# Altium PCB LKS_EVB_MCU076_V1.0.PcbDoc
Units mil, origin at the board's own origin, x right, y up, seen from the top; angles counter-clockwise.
Board outline 2625 x 1560 mil, 2 copper layers (Top Layer, Bottom Layer); 44 components, 69 nets, 198 pads, 50 vias.
Unrouted connection lines stored in the file: 4.
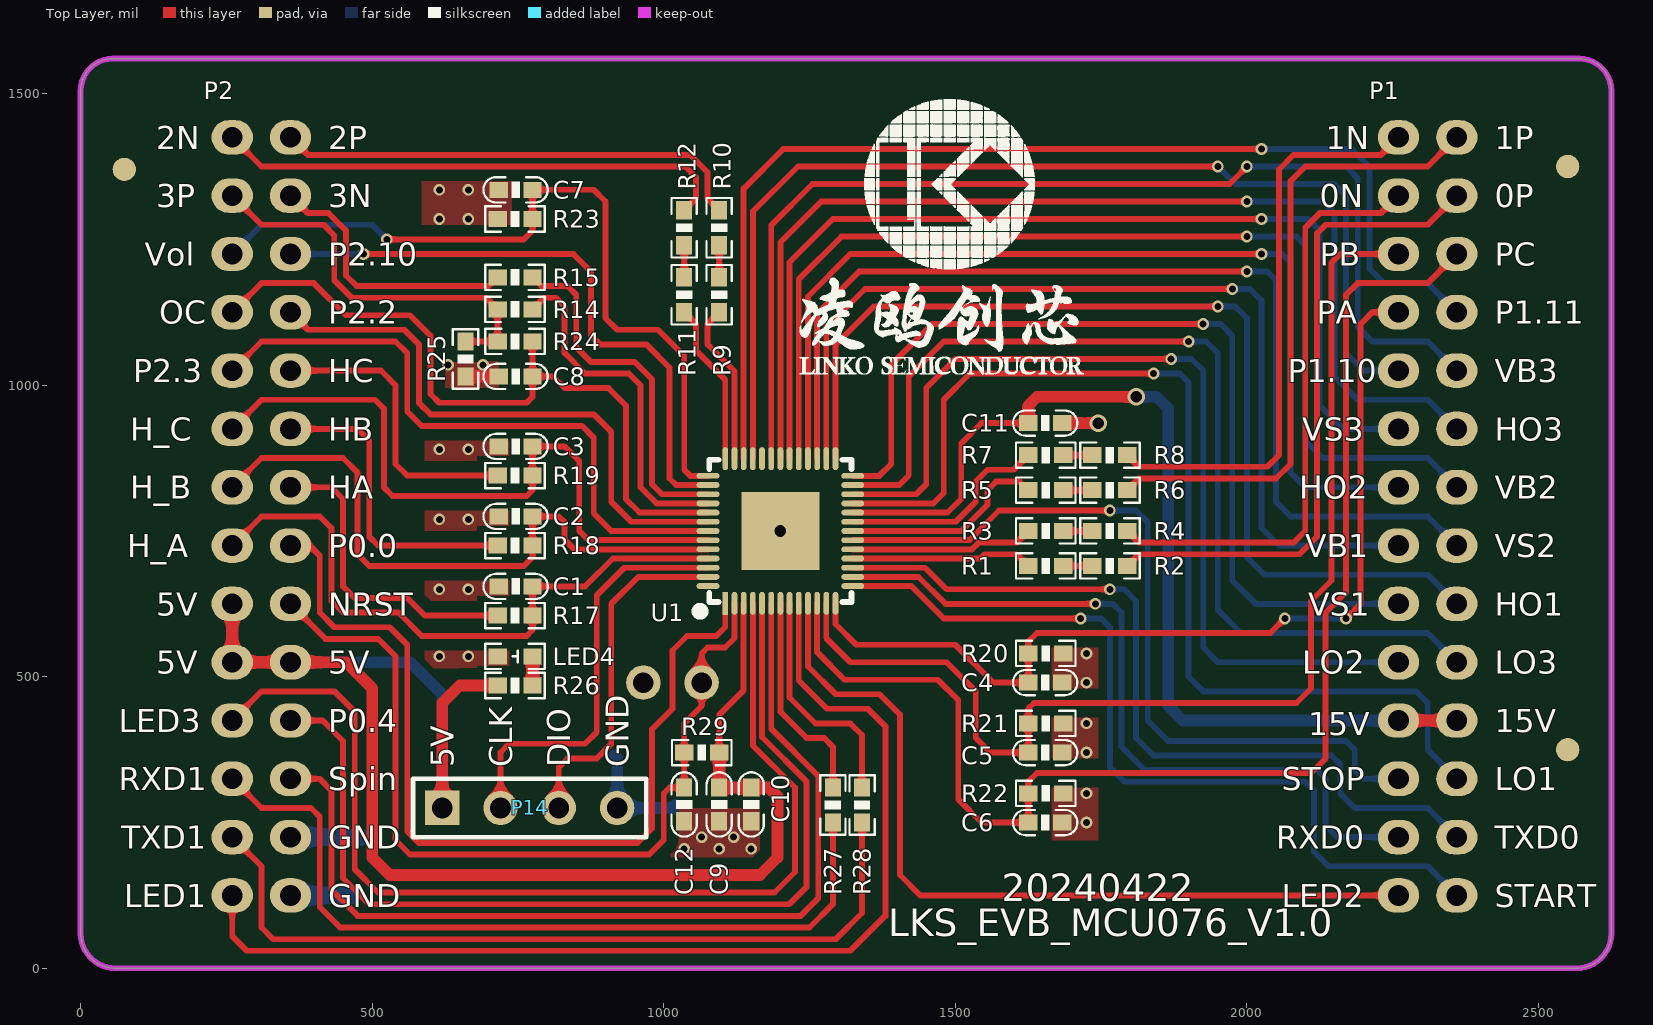
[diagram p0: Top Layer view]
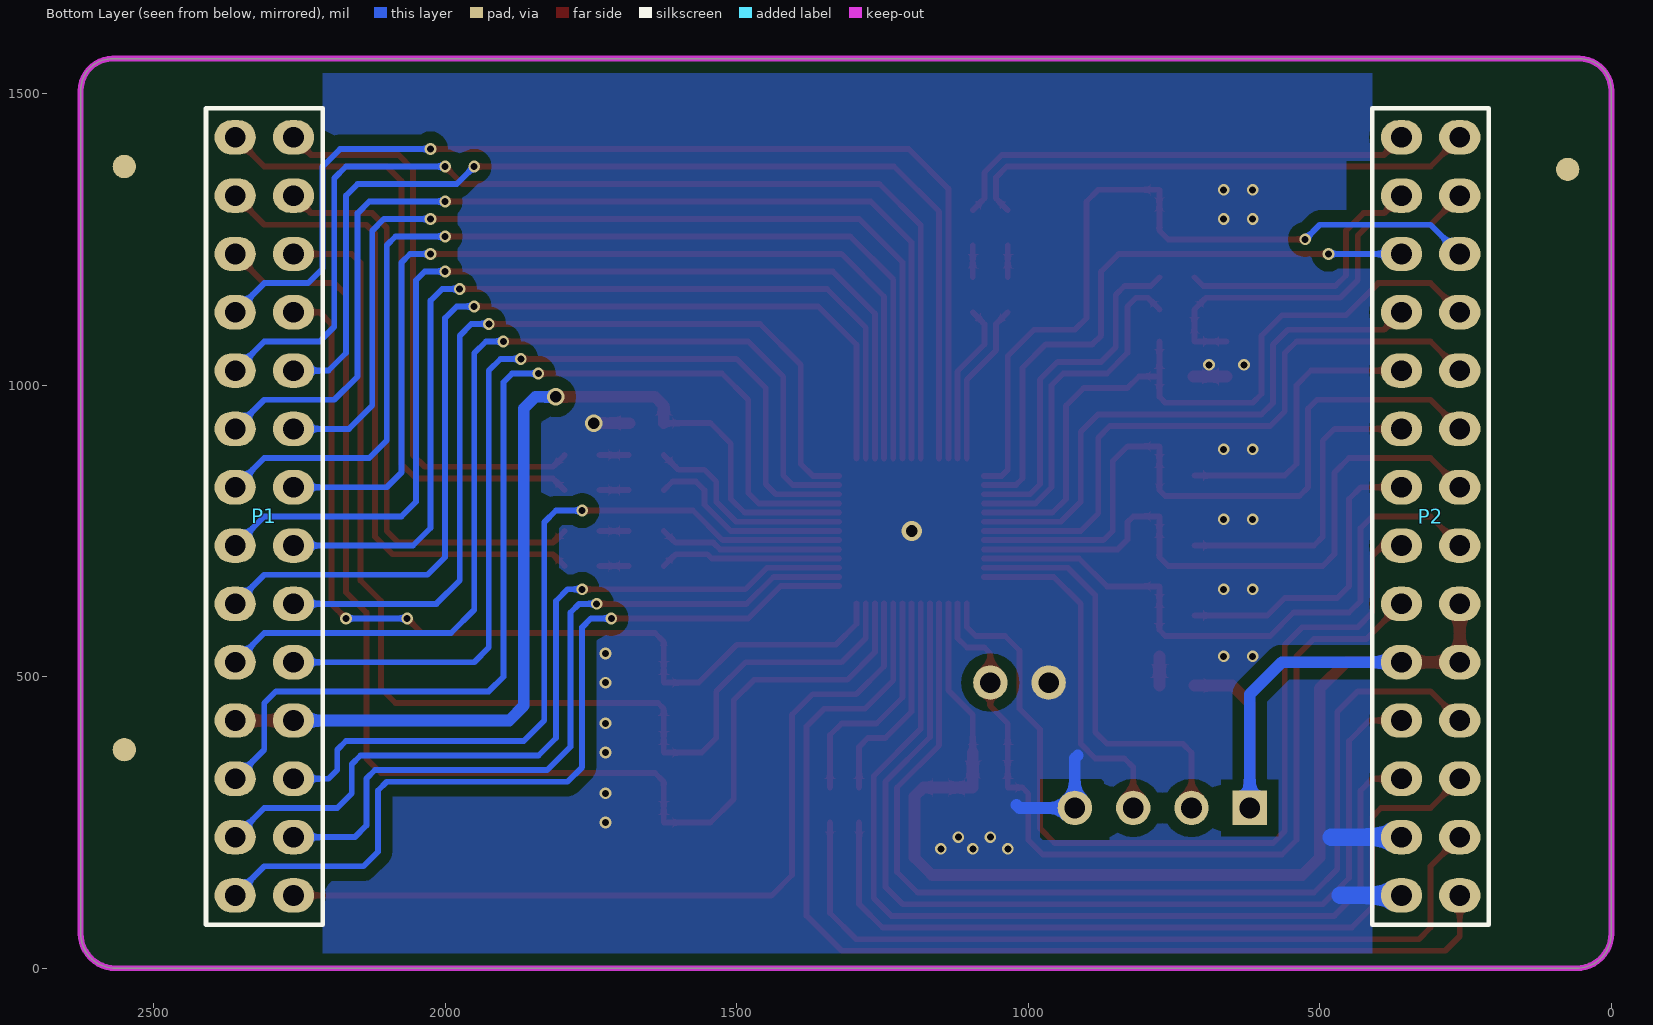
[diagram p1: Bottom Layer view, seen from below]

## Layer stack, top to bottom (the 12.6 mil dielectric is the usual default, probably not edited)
Top Solder: solder mask 0.4, Solder Resist, Dk 3.5
Top Layer: signal copper 1.4
Dielectric1: dielectric 12.6, FR-4, Dk 4.8
Bottom Layer: signal copper 1.4
Bottom Solder: solder mask 0.4, Solder Resist, Dk 3.5

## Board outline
0,60 0,1505 cw(c55,1505) 55,1560 2570,1560 cw(c2570,1505) 2625,1505 2625,60 cw(c2565,60) 2565,0 60,0 cw(c60,60)

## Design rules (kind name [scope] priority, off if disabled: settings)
Clearance Clearance_1 [InPolygon] p1: gap=20 ignorepadtopadclearanceinfootprint=FALSE except(0: Arc-Hole Track-Hole SMDPad-Hole THPad-Hole Via-Hole Fill-Hole Poly-Hole Region-Hole Text-Hole)
Clearance [All] p2: gap=3 ignorepadtopadclearanceinfootprint=FALSE except(0: Arc-Hole Track-Hole SMDPad-Hole THPad-Hole Via-Hole Fill-Hole Poly-Hole Region-Hole Text-Hole)
ComponentClearance [All] p1: gap=0 collisioncheckmode=3 verticalgap=0 showdistances=FALSE
FabricationTestpoint [(IsPad And (OnTopLayer Or OnBottomLayer))] p1: side=3 testpointundercomponent=TRUE minsize=40 maxsize=100 preferedsize=60 minholesize=0 maxholesize=40 preferedholesize=32 testpointgrid=1 allowsidetop=TRUE allowsidebottom=TRUE usegrid=TRUE gridtolerance=0.01
PolygonConnect [All] p1: connectstyle=Direct reliefconductorwidth=25 reliefentries=4 polygonreliefangle="90 Angle" airgapwidth=10
RoutingVias [All] p1: holewidth=28 width=50 viastyle="Through Hole" minholewidth=0 minwidth=10 maxholewidth=20 maxwidth=100
SilkToSolderMaskClearance SilkscreenOverComponentPads [IsPad] p1: minsilkscreentomaskgap=10 clearancetoexposedcopper=TRUE
SolderMaskExpansion [All] p1: expansion=4 istentingtop=FALSE
Width [All] p1: maxlimit=100 minlimit=2 preferedwidth=10
27 further rules are at their usual default settings.

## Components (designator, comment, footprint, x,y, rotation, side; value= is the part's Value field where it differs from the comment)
C1 "10nF/16V" 0603C 746,655 r180 top
C2 "10nF/16V" 0603C 746,775 r180 top
C3 "10nF/16V" 0603C 746,895 r180 top
C4 "1nF/50V" 0603C 1654,490 r0 top
C5 "1nF/50V" 0603C 1654,370 r0 top
C6 "1nF/50V" 0603C 1654,250 r0 top
C7 "100nF/50V" 0603C 745.95,1335 r0 top
C8 "1nF/50V" 0603C 745.95,1015 r0 top
C9 "10uF/16V" 0603C 1095,280.95 r90 top
C10 "100nF/50V" 0603C 1150,280.95 r90 top
C11 "4.7uF/35V" 0603C 1654.06,935 r180 top
C12 "100nF/50V" 0603C 1035,281 r270 top
LED4 "LED" "LED 0603R" 745,535 r0 top
P1 "Header 14X2A" "HDR 2X14 底层" 2260,1425 r180 bottom locked
P2 "Header 14X2A" "HDR 2X14 底层" 260,1425 r180 bottom locked
P14 "Header 4" "HDR 1X4" 620,275 r0 top
R1 "20K1%" 0603R 1655,690 r180 top value=K
R2 "20K1%" 0603R 1765,690 r180 top value=K
R3 "20K1%" 0603R 1655,750 r180 top value=K
R4 "20K1%" 0603R 1765,750 r180 top value=K
R5 "20K1%" 0603R 1655,820 r180 top value=K
R6 "20K1%" 0603R 1765,820 r180 top value=K
R7 "20K1%" 0603R 1655,880 r180 top value=K
R8 "20K1%" 0603R 1765,880 r180 top value=K
R9 "20K1%" 0603R 1095,1155 r270 top value=K
R10 "20K1%" 0603R 1095,1270 r270 top value=K
R11 "20K1%" 0603R 1035,1155 r270 top value=K
R12 "20K1%" 0603R 1035,1270 r270 top value=K
R14 "1K1%" 0603R 745,1130 r0 top value=K
R15 "1K1%" 0603R 745,1185 r0 top value=K
R17 "2K" 0603R 745,605 r0 top value=K
R18 "2K" 0603R 745,725 r0 top value=K
R19 "2K" 0603R 745,845 r0 top value=K
R20 "1K" 0603R 1655,540 r0 top value=K
R21 "1K" 0603R 1655,420 r0 top value=K
R22 "1K" 0603R 1655,300 r0 top value=K
R23 "1K1%" 0603R 745,1285 r0 top value=K
R24 "1K1%" 0603R 745,1075 r180 top value=K
R25 "10R" 0603R 660,1045 r270 top value=10
R26 "330R" 0603R 745,485 r0 top value=330
R27 "10R" 0603R 1290,280 r270 top
R28 "10R" 0603R 1340,280 r90 top value=100R
R29 "20K" 0603R 1065,370 r180 top value=K
U1 "LKS32MC076NBQ8" QFN52 1200,750 r90 top locked

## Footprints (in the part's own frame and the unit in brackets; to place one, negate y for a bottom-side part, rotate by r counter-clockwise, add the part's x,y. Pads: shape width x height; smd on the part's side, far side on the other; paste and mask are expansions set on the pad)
0603C [mm] "电容"
  rect 0.8x0.7 smd: 1(-0.737,0) 2(0.738,0)
  silkscreen extent -1.4,-0.55 1.4,0.55, body extent -0.8,-0.41 0.8,0.41, height 0.81
0603R [mm] "电阻"
  rect 0.8x0.7 smd: 1(-0.762,0) 2(0.762,0)
  silkscreen extent -1.3,-0.55 1.3,0.55, body extent -0.8,-0.4 0.8,0.4, height 0.45
"HDR 1X4" [mm] "单排针 2.54mm"
  rect 1.5x1.5 hole 0.9: 1(0,0)
  round 1.5 hole 0.9: 2(2.54,0) 3(5.08,0) 4(7.62,0)
  silkscreen extent -1.27,-1.27 8.89,1.27, body extent -1.27,-1.27 8.89,1.27, height 8.5
"HDR 2X14 底层" [mm] "双排针 2.54mm 底层"
  oval 1.8x1.5 hole 0.9: 1(0,0) 2(0,-2.54) 3(0,-5.08) 4(0,-7.62) 5(0,-10.16) 6(0,-12.7) 7(0,-15.24) 8(0,-17.78) 9(0,-20.32) 10(0,-22.86) 11(0,-25.4) 12(0,-27.94) 13(0,-30.48) 14(0,-33.02) 15(-2.54,0) 16(-2.54,-2.54) 17(-2.54,-5.08) 18(-2.54,-7.62) 19(-2.54,-10.16) 20(-2.54,-12.7) 21(-2.54,-15.24) 22(-2.54,-17.78) 23(-2.54,-20.32) 24(-2.54,-22.86) 25(-2.54,-25.4) 26(-2.54,-27.94) 27(-2.54,-30.48) 28(-2.54,-33.02)
  silkscreen extent -3.81,-34.29 1.27,1.27, body extent -3.81,-34.29 1.27,1.27, height 8.5
"LED 0603R" [mm] "LED"
  rect 0.8x0.7 smd: 1(0.762,0) 2(-0.762,0)
  silkscreen extent -1.3,-0.55 1.3,0.55, body extent -0.8,-0.4 0.8,0.4, height 0.47
QFN52 [mm] "LINKO-086"
  rect 3.4x3.4 smd: 0(0,0)
  rect 1x0.25 smd: 1(-3.15,2.4)
  oval 1x0.25 smd: 2(-3.15,2) 3(-3.15,1.6) 4(-3.15,1.2) 5(-3.15,0.8) 6(-3.15,0.4) 7(-3.15,0) 8(-3.15,-0.4) 9(-3.15,-0.8) 10(-3.15,-1.2) 11(-3.15,-1.6) 12(-3.15,-2) 13(-3.15,-2.4) 27(3.15,-2.4) 28(3.15,-2) 29(3.15,-1.6) 30(3.15,-1.2) 31(3.15,-0.8) 32(3.15,-0.4) 33(3.15,0) 34(3.15,0.4) 35(3.15,0.8) 36(3.15,1.2) 37(3.15,1.6) 38(3.15,2) 39(3.15,2.4)
  oval 0.25x1 smd: 14(-2.4,-3.15) 15(-2,-3.15) 16(-1.6,-3.15) 17(-1.2,-3.15) 18(-0.8,-3.15) 19(-0.4,-3.15) 20(0,-3.15) 21(0.4,-3.15) 22(0.8,-3.15) 23(1.2,-3.15) 24(1.6,-3.15) 25(2,-3.15) 26(2.4,-3.15) 40(2.4,3.15) 41(2,3.15) 42(1.6,3.15) 43(1.2,3.15) 44(0.8,3.15) 45(0.4,3.15) 46(0,3.15) 47(-0.4,3.15) 48(-0.8,3.15) 49(-1.2,3.15) 50(-1.6,3.15) 51(-2,3.15) 52(-2.4,3.15)
  silkscreen extent -3.61,-3.1 3.1,3.61, body extent -3,-3 3,3, height 0.9

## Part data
C1 C2 C3 C4 C5 C6: library part CAP, "Capacitor"
C7 C8 C9 C10 C11 C12: library part C, "Capacitor"
LED4: "LED_Light"
P1 P2: "Header, 14-Pin, Dual row"
P14: "Header, 4-Pin"
R1 R2 R3 R4 R5 R6 R7 R8 R9 R10 R11 R12 R14 R15 R17 R18 R19 R20 R21 R22 R23 R24 R25 R26 R29: library part Res, "Resistor"
R27 R28: library part Res2, "Resistor"

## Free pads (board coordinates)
  round 59.06 hole 35.43: 0(1065,490) 1(965,490)
  round 40 all layers, no hole: 1(75,1370) 2(2550,375) 3(2550,1375)

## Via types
v1: diameter 20, hole 12, Top Layer to Bottom Layer, 47 vias
v2: diameter 30, hole 20, Top Layer to Bottom Layer, 2 vias
v3: diameter 35, hole 20, Top Layer to Bottom Layer, 1 vias

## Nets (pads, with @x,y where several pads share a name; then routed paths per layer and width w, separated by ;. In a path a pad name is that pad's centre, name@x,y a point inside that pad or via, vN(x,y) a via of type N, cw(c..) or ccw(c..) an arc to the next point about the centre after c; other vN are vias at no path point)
+5V: C9.2 C10.2 P2.9 P2.10 P2.24 P14.1 R26.1 R29.1 U1.3 | length 2678.3
  Top Layer w10: R29.1 1095,435 1137.01,477.01 U1.3
  Top Layer w20: P2.9 P2.10 P2.24 455,525 500,480 500,190 530,160 1165,160 1195,190 1195,295 1180,310 C10.2 C9.2 R29.1 ; P14.1 620,455 650,485 R26.1
  Bottom Layer w20: P2.24 565,525 620,470 P14.1
+15V: C11.2 P1.11 P1.25 U1.22 | length 1720.1
  Top Layer w10: U1.22 1486.5,781.5 1510,805 1510,900 1545,935 C11.2
  Top Layer w20: C11.2 1625,965 1640,980 v2(1810,980) ; P1.11 P1.25
  Bottom Layer w20: v2(1810,980) 1845,980 1865,960 1865,450 1890,425 P1.11
GND: C1.2 C2.2 C3.2 C4.2 C5.2 C6.2 C7.1 C8.1 C9.1 C10.1 C11.1 C12.2 LED4.2 P2.16 P2.27 P2.28 P14.4 pad.1@965,490 R15.1 R20.2 R21.2 R22.2 R23.1 R25.2 U1.0 | length 1008.4
  Top Layer w10: P2.16 390,1295 425,1295 455,1265 455,1188.28 473.28,1170 700,1170 R15.1
  Top Layer w20: R25.2 C8.1 ; C11.1 v2(1745,935)
  Bottom Layer w20: 915,365 920,360 P14.4 1015,275 1020,280
  Bottom Layer w30: P2.28 465,125 ; P2.27 480,225
  other v1: 1035,205 1095,205 1150,205 1065,225 1120,225 1725,250 1725,300 1725,370 1725,420 1725,490 615,535 665,535 1725,540 615,650 665,650 615,770 665,770 615,890 665,890 630,1035 690,1035 615,1285 665,1285 615,1335 665,1335
  other v3: 1200,750
HALL_U: C1.1 P2.8 R17.2 U1.49 | length 1093.8
  Top Layer w10: P2.8 310,775 410,775 430,755 430,630 450,610 545,610 585,570 765,570 775,580 R17.2 C1.1 865,655 912.76,702.76 U1.49
HALL_V: C2.1 P2.7 R18.2 U1.48 | length 1112.5
  Top Layer w10: P2.7 310,875 450,875 475,850 475,710 495,690 760,690 775,705 R18.2 C2.1 820,775 830,765 830,735 846.5,718.5 U1.48
HALL_W: C3.1 P2.6 R19.2 U1.47 | length 1200.1
  Top Layer w10: P2.6 310,975 505,975 520,960 520,825 535,810 765,810 775,820 R19.2 C3.1 830,895 855,870 855,750 870.75,734.25 U1.47
HO1: P1.23 U1.27 | length 1739.5
  Top Layer w10: U1.27 1294.49,1069.49 1360,1135 v1(1950,1135)
  Bottom Layer w10: v1(1950,1135) 1980,1135 2000,1115 2000,705 2030,675 2310,675 P1.23
HO2: P1.7 U1.30 | length 1697.7
  Top Layer w10: U1.30 1247.24,1152.24 1320,1225 v1(2025,1225)
  Bottom Layer w10: v1(2025,1225) 2060,1225 2075,1210 2075,850 2100,825 P1.7
HO3: P1.20 U1.33 | length 1885.5
  Top Layer w10: U1.33 1200,1245 1270,1315 v1(2000,1315)
  Bottom Layer w10: v1(2000,1315) 2130,1315 2150,1295 2150,1015 2190,975 2310,975 P1.20
HU: P2.21 R17.1 | length 534
  Top Layer w10: P2.21 430,825 450,805 450,655 470,635 560,635 590,605 R17.1
HV: P2.20 R18.1 | length 534.5
  Top Layer w10: P2.20 475,925 495,905 495,740 510,725 R18.1
HW: P2.19 R19.1 | length 508.6
  Top Layer w10: P2.19 515,1025 540,1000 540,865 560,845 R19.1
LED1: P2.14 U1.9 | length 1863.7
  Top Layer w10: P2.14 260,55 285,30 1320,30 1380,90 1380,415 1350,445 1280,445 1231.5,493.5 U1.9
LED2: P1.14 U1.10 | length 1444.8
  Top Layer w10: U1.10 1247.24,517.76 1295,470 1370,470 1405,435 1405,160 1440,125 P1.14
LED3: P2.11 U1.4 | length 1792.2
  Top Layer w10: P2.11 310,475 435,475 470,440 470,170 510,130 1190,130 1225,165 1225,310 1152.76,382.24 U1.4
LO1: P1.26 U1.23 | length 1852.5
  Top Layer w10: U1.23 1462.24,797.24 1480,815 1480,975 1525,1020 v1(1840,1020)
  Bottom Layer w10: v1(1840,1020) 1885,1020 1900,1005 1900,500 1925,475 2290,475 2310,455 2310,375 P1.26
LO2: P1.10 U1.24 | length 1622.4
  Top Layer w10: U1.24 1432.99,812.99 1450,830 1450,995 1500,1045 v1(1870,1045)
  Bottom Layer w10: v1(1870,1045) 1905,1045 1925,1025 1925,550 1950,525 P1.10
LO3: P1.24 U1.25 | length 1723.1
  Top Layer w10: U1.25 1403.74,828.74 1420,845 1420,1015 1480,1075 v1(1900,1075)
  Bottom Layer w10: v1(1900,1075) 1930,1075 1950,1055 1950,615 1990,575 2310,575 P1.24
NC: U1.35
NetLED4_1: LED4.1 R26.2 | length 50
  Top Layer w20: R26.2 LED4.1
NetR1_1: R1.1 R2.2 | length 50
  Top Layer w10: R1.1 R2.2
NetR3_1: R3.1 R4.2 | length 50
  Top Layer w10: R3.1 R4.2
NetR5_1: R5.1 R6.2 | length 50
  Top Layer w10: R5.1 R6.2
NetR7_1: R7.1 R8.2 | length 50
  Top Layer w10: R7.1 R8.2
NetR9_1: R9.1 R10.2 | length 55
  Top Layer w10: R9.1 R10.2
NetR11_1: R11.1 R12.2 | length 55
  Top Layer w10: R11.1 R12.2
NetR27_1: R27.1 U1.7 | length 370.8
  Top Layer w10: U1.7 1200,440 1245,395 1275,395 1290,380 R27.1
NetR28_2: R28.2 U1.8 | length 402.6
  Top Layer w10: U1.8 1215.75,464.25 1260,420 1320,420 1340,400 R28.2
NRST: C12.1 P2.23 pad.0 R29.2 U1.2 | length 1501.4
  Top Layer w10: P2.23 420,565 510,565 540,535 540,220 565,195 975,195 1000,220 1000,300 1010,310 C12.1 R29.2 1035,420 1065,450 pad.0 1065,540 1075,550 1105,550 1121.26,566.26 U1.2
OC: C8.2 P2.4 R24.1 U1.44 | length 1269.8
  Top Layer w10: P2.4 310,1175 400,1175 455,1120 565,1120 600,1085 600,985 615,970 765,970 775,980 C8.2 ; R24.1 C8.2 ; U1.44 958.5,781.5 935,805 935,965 905,995 830,995 810,1015 C8.2
OPA0_IN: R3.2 U1.18 | length 314
  Top Layer w10: U1.18 1476.5,718.5 1528.5,718.5 1540,730 1605,730 R3.2
OPA0_IP: R1.2 U1.17 | length 312.3
  Top Layer w10: U1.17 1462.24,702.76 1542.76,702.76 1550,710 1605,710 R1.2
OPA1_IN: R7.2 U1.21 | length 368.8
  Top Layer w10: U1.21 1500.75,765.75 1535,800 1535,835 1555,855 1600,855 R7.2
OPA1_IP: R5.2 U1.20 | length 357.1
  Top Layer w10: U1.20 1510,750 1555,795 1555,820 1570,835 1610,835 R5.2
OPA2_IN: R11.2 U1.39 | length 280.2
  Top Layer w10: R11.2 1055,1105 1055,1060 1105.51,1009.49 U1.39
OPA2_IP: R9.2 U1.38 | length 278.4
  Top Layer w10: R9.2 1075,1105 1075,1070 1121.26,1023.74 U1.38
OPA3_IN: R15.2 U1.42 | length 613.2
  Top Layer w10: R15.2 790,1170 835,1170 850,1155 850,1065 875,1040 950,1040 980,1010 980,830 997.01,812.99 U1.42
OPA3_IP: R14.2 U1.43 | length 604.8
  Top Layer w10: R14.2 795,1150 815,1150 830,1135 830,1055 865,1020 940,1020 960,1000 960,825 987.76,797.24 U1.43
P0.0: P2.22 U1.1 | length 1553.4
  Top Layer w10: P2.22 392.5,725 410,707.5 410,610 435,585 530,585 560,555 560,235 580,215 955,215 980,240 980,410 1015,445 1015,545 1040,570 1090,570 1105.51,585.51 U1.1
P0.4: P2.25 U1.5 | length 1683.2
  Top Layer w10: P2.25 415,425 450,390 450,155 495,110 1215,110 1245,140 1245,320 1168.5,396.5 U1.5
P1.10: P1.5 U1.36 | length 1866.1
  Top Layer w10: U1.36 1152.76,1297.76 1230,1375 v1(1950,1375)
  Bottom Layer w10: v1(1950,1375) 1980,1345 2150,1345 2170,1325 2170,1055 2200,1025 P1.5
P1.11: P1.18 U1.37 | length 1932.6
  Top Layer w10: U1.37 1137.01,1337.01 1205,1405 v1(2024.94,1405)
  Bottom Layer w10: v1(2024.94,1405) 2180,1405 2210,1375 2210,1200 2235,1175 2310,1175 P1.18
P2.2: P2.18 U1.45 | length 993.7
  Top Layer w10: P2.18 390,1095 555,1095 580,1070 580,970 600,950 880,950 910,920 910,800 944.25,765.75 U1.45
P2.3: P2.5 U1.46 | length 1106
  Top Layer w10: P2.5 310,1075 540,1075 560,1055 560,955 585,930 860,930 880,910 880,780 910,750 U1.46
P2.10: P2.17 U1.41 | length 1055.9
  Top Layer w10: v1(485,1225) 845,1225 875,1195 875,1085 890,1070 970,1070 1010,1030 1010,840 1021.26,828.74 U1.41
  Bottom Layer w10: P2.17 v1(485,1225)
P2.15: U1.52
PGND: P1.1 P1.2 P2.1 P2.2 R4.1 R8.1 R12.1 R14.1 R24.2 R25.1 | length 3597.7
  Top Layer w10: P2.2 310,1275 416.72,1275 435,1256.72 435,1180 465,1150 695,1150 R14.1 R24.2 R25.1 ; P2.1 310,1375 1036.72,1375 1055,1356.72 1055,1320 R12.1 ; R4.1 1815,730 2080,730 2100,750 2100,1270 2125,1295 2230,1295 P1.2 ; R8.1 1815,860 2035,860 2055,880 2055,1370 2080,1395 2230,1395 P1.1
PU: C4.1 P1.4 R20.1 U1.13 | length 1627.8
  Top Layer w10: U1.13 1294.49,590.51 1330,555 1500,555 1565,490 C4.1 R20.1 1625,560 1640,575 2040,575 v1(2065,600) ; v1(2170,600) 2195,625 2195,1105 2215,1125 P1.4
  Bottom Layer w10: v1(2065,600) v1(2170,600)
PV: C5.1 P1.3 R21.1 U1.12 | length 1974.3
  Top Layer w10: U1.12 1278.74,566.26 1320,525 1485,525 1535,475 1535,395 1560,370 C5.1 R21.1 1625,445 1635,455 2085,455 2110,480 2110,630 2145,665 2145,1210 2160,1225 P1.3
PW: C6.1 P1.17 R22.1 U1.11 | length 2291.6
  Top Layer w10: U1.11 1262.99,542.01 1310,495 1470,495 1505,460 1505,290 1545,250 C6.1 R22.1 1625,320 1640,335 2110,335 2135,360 2135,610 2170,645 2170,1155 2190,1175 2310,1175 P1.17
RXD0: P1.13 U1.15 | length 1302.4
  Top Layer w10: U1.15 1436.74,671.26 1483,625 v1(1740,625)
  Bottom Layer w10: v1(1740,625) 1770,625 1785,610 1785,380 1825,340 2120,340 2135,325 2135,245 2155,225 P1.13
RXD1: P2.12 R27.2 | length 1383
  Top Layer w10: P2.12 310,275 395,275 410,260 410,105 445,70 1250,70 1290,110 R27.2
SPIN: P2.26 U1.6 | length 1653.8
  Top Layer w10: P2.26 410,325 430,305 430,135 475,90 1235,90 1265,120 1265,330 1184.25,410.75 U1.6
START1: P1.28 U1.14 | length 1457.8
  Top Layer w10: U1.14 1424.49,655.51 1480,600 v1(1715,600)
  Bottom Layer w10: v1(1715,600) 1750,600 1765,585 1765,345 1790,320 2100,320 2115,305 2115,200 2140,175 2310,175 P1.28
STOP1: P1.12 U1.19 | length 1367.2
  Top Layer w10: U1.19 1524.25,734.25 1575,785 v1(1765,785)
  Bottom Layer w10: v1(1765,785) 1810,785 1830,765 1830,425 1865,390 2170,390 2185,375 2185,340 2200,325 P1.12
SWCLK: P14.2 U1.50 | length 720
  Top Layer w10: P14.2 720,370 735,385 865,385 885,405 885,640 932.01,687.01 U1.50
SWDIO: P14.3 U1.51 | length 601.7
  Top Layer w10: P14.3 820,345 835,360 885,360 910,385 910,625 956.26,671.26 U1.51
TXD0: P1.27 U1.16 | length 1394.3
  Top Layer w10: U1.16 1447.99,687.01 1485,650 v1(1765,650)
  Bottom Layer w10: v1(1765,650) 1790,650 1810,630 1810,395 1840,365 2145,365 2160,350 2160,300 2185,275 2310,275 P1.27
TXD1: P2.13 R28.1 | length 1387.6
  Top Layer w10: P2.13 310,175 310,70 330,50 1295,50 1340,95 R28.1
UP-: P2.15 R10.1 | length 813.1
  Top Layer w10: P2.15 390,1395 1045,1395 1075,1365 1075,1320 R10.1
VB1: P1.8 U1.28 | length 1644.1
  Top Layer w10: U1.28 1278.74,1098.74 1345,1165 v1(1975,1165)
  Bottom Layer w10: v1(1975,1165) 2005,1165 2025,1145 2025,755 2055,725 P1.8
VB2: P1.21 U1.31 | length 1840.8
  Top Layer w10: U1.31 1231.5,1181.5 1305,1255 v1(2000,1255)
  Bottom Layer w10: v1(2000,1255) 2085,1255 2100,1240 2100,905 2130,875 2310,875 P1.21
VB3: P1.19 U1.34 | length 1912.1
  Top Layer w10: U1.34 1184.25,1274.25 1255,1345 1970,1345 v1(2000,1375)
  Bottom Layer w10: v1(2000,1375) 2170,1375 2190,1355 2190,1100 2215,1075 2310,1075 P1.19
VOL_ADC: C7.2 P2.3 R23.2 U1.40 | length 1357.8
  Top Layer w10: v1(525,1250) 760,1250 775,1265 R23.2 C7.2 880,1335 900,1315 900,1115 920,1095 990,1095 1035,1050 1035,855 1045.51,844.49 U1.40
  Bottom Layer w10: P2.3 310,1275 500,1275 v1(525,1250)
VP-: P1.15 R6.1 | length 1099.7
  Top Layer w10: R6.1 1815,840 2050,840 2075,865 2075,1350 2100,1375 2310,1375 P1.15
VS1: P1.9 U1.26 | length 1588.3
  Top Layer w10: U1.26 1369.49,844.49 1390,865 1390,1035 1460,1105 v1(1925,1105)
  Bottom Layer w10: v1(1925,1105) 1955,1105 1975,1085 1975,665 2015,625 P1.9
VS2: P1.22 U1.29 | length 1793.1
  Top Layer w10: U1.29 1262.99,1122.99 1335,1195 v1(2000,1195)
  Bottom Layer w10: v1(2000,1195) 2035,1195 2050,1180 2050,800 2075,775 2310,775 P1.22
VS3: P1.6 U1.32 | length 1736.6
  Top Layer w10: U1.32 1215.75,1210.75 1290,1285 v1(2025,1285)
  Bottom Layer w10: v1(2025,1285) 2105,1285 2125,1265 2125,965 2165,925 P1.6
WP-: P1.16 R2.1 | length 1132.6
  Top Layer w10: R2.1 1815,710 2090,710 2120,740 2120,1260 2135,1275 2310,1275 P1.16

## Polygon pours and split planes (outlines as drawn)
GND on Top Layer "NONET_L-01_P-001" (solid, remove dead copper, pour order 13): 735,515 605,515 590,530 590,915 610,935 735,935
GND on Top Layer "NONET_L-01_P-001" (solid, remove dead copper, pour order 15): 740,1375 740,1260 730,1250 605,1250 585,1270 585,1355 605,1375
GND on Top Layer "NONET_L-01_P-001" (solid, remove dead copper, pour order 14): 615,1055 700,1055 716.95,1038.05 716.95,986.95 705,975 620,975 615,980
GND on Top Layer "NONET_L-01_P-001" (solid, remove dead copper, pour order 12): 1665,575 1665,220 1745,220 1745,575
GND on Top Layer "NONET_L-01_P-001" (solid, remove dead copper, pour order 11): 1010,280 1195,280 1195,190 1165,160 1010,160
GND on Bottom Layer "Bottom Layer-No Net 1" (solid, remove dead copper, pour order 10): 410,1560 410,0 2210,0 2210,1560

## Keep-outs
Keep-Out Layer:
  the board outline again, w10

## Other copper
Bottom Layer:
  pour cut-out: 870,320 875,325 980,325 980,225 975,220 860,220
  pour cut-out: 315,1380 320,1385 455,1385 455,1270 445,1260 320,1260

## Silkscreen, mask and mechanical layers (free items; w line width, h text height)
Top Overlay:
  drawing of 144 lines, arcs and shapes, not listed
  text "2N" at 130,1405 h39.37
  text "2P" at 425,1405 h39.37
  text "1N" at 2135,1405 h39.37
  text "1P" at 2425,1405 h39.37
  text "3P" at 130,1305 h39.37
  text "3N" at 425,1305 h39.37
  text "0N" at 2125,1305 h39.37
  text "0P" at 2425,1305 h39.37
  text "Vol" at 110,1205 h39.37
  text "P2.10" at 425,1205 h39.37
  text "PB" at 2125,1205 h39.37
  text "PC" at 2425,1205 h39.37
  text "OC" at 135,1105 h39.37
  text "P2.2" at 425,1105 h39.37
  text "PA" at 2120,1105 h39.37
  text "P1.11" at 2425,1105 h39.37
  text "P2.3" at 90,1005 h39.37
  text "HC" at 425,1005 h39.37
  text "P1.10" at 2070,1005 h39.37
  text "VB3" at 2425,1005 h39.37
  text "H_C" at 85,905 h39.37
  text "HB" at 425,905 h39.37
  text "VS3" at 2095,905 h39.37
  text "HO3" at 2425,905 h39.37
  text "H_B" at 85,805 h39.37
  text "HA" at 425,805 h39.37
  text "HO2" at 2090,805 h39.37
  text "VB2" at 2425,805 h39.37
  text "H_A" at 80,705 h39.37
  text "P0.0" at 425,705 h39.37
  text "VB1" at 2100,705 h39.37
  text "VS2" at 2425,705 h39.37
  text "5V" at 130,605 h39.37
  text "NRST" at 425,605 h39.37
  text "VS1" at 2105,605 h39.37
  text "HO1" at 2425,605 h39.37
  text "5V" at 130,505 h39.37
  text "5V" at 425,505 h39.37
  text "LO2" at 2095,505 h39.37
  text "LO3" at 2425,505 h39.37
  text "LED3" at 65,405 h39.37
  text "P0.4" at 425,405 h39.37
  text "15V" at 2425,405 h39.37
  text "15V" at 2105,400 h39.37
  text "5V" at 640,345 h39.37 r90
  text "CLK" at 740,345 h39.37 r90
  text "DIO" at 840,345 h39.37 r90
  text "GND" at 940,345 h39.37 r90
  text "RXD1" at 65,305 h39.37
  text "Spin" at 425,305 h39.37
  text "STOP" at 2060,305 h39.37
  text "LO1" at 2425,305 h39.37
  text "TXD1" at 70,205 h39.37
  text "GND" at 425,205 h39.37
  text "RXD0" at 2050,205 h39.37
  text "TXD0" at 2425,205 h39.37
  text "LED1" at 75,105 h39.37
  text "GND" at 425,105 h39.37
  text "LED2" at 2060,105 h39.37
  text "START" at 2425,105 h39.37
  text "20240422" at 1580,100 h80
  text "LKS_EVB_MCU076_V1.0" at 1385,40 h80
Top Solder:
  circle w78: c2550,1375 r17
  circle w78: c2550,375 r17
  circle w78: c75,1370 r17
Mechanical 1:
  the board outline again, w10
